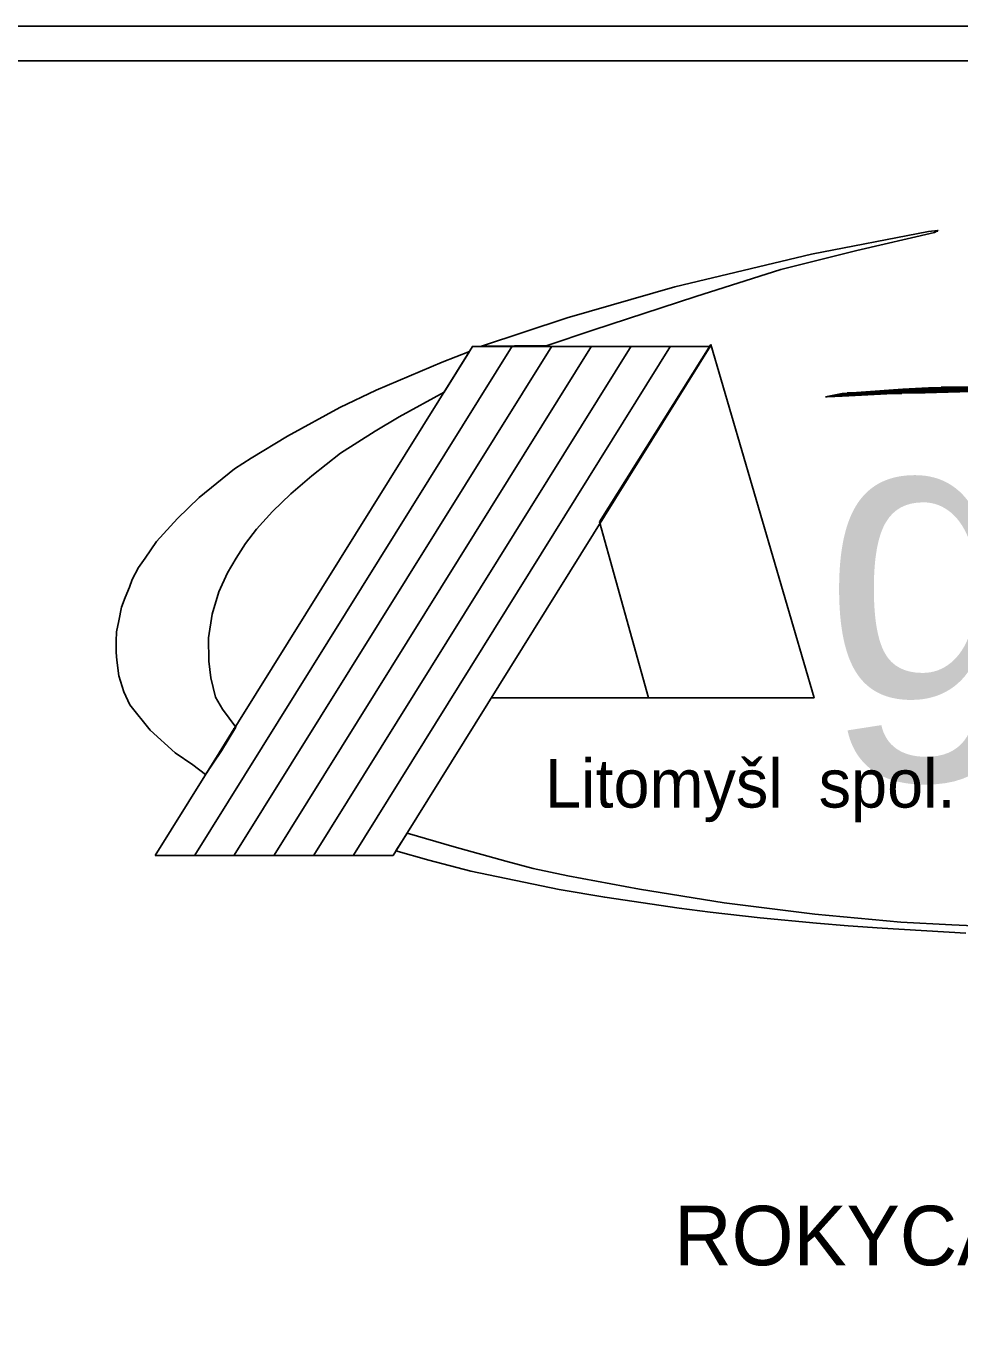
# Model space of a CAD drawing. Extents: x -5481 to -5365, y -3322 to -3178.
# Drawn here: x -5371.921 to -5369.567, y -3316.108 to -3312.83 of the extents above; entities that cross this region are included whole.
import ezdxf

# ---------------------------------------------------------------- set-up
doc = ezdxf.new("R2010")
doc.units = 0
doc.layers.add('Nová vrstva (0)', color=7, linetype='Continuous')

msp = doc.modelspace()

# ---------------------------------------------------------------- linework, layer by layer
at = {"layer": 'Nová vrstva (0)'}
for p, q in [((-5369.6242, -3313.347), (-5369.6232, -3313.347)), ((-5369.6198, -3313.346), (-5369.6195, -3313.346)), ((-5371.4954, -3314.9204), (-5370.696, -3313.6369)), ((-5371.3961, -3314.9204), (-5370.5962, -3313.6369)), ((-5371.2956, -3314.9204), (-5370.4962, -3313.6369)), ((-5371.1957, -3314.9204), (-5370.3963, -3313.6369)), ((-5371.1957, -3314.9204), (-5370.3963, -3313.6369)), ((-5371.0957, -3314.9204), (-5370.2964, -3313.6369)), ((-5369.9059, -3313.7651), (-5369.9018, -3313.7651)), ((-5369.9018, -3313.7639), (-5369.8828, -3313.7639)), ((-5369.8976, -3313.7629), (-5369.8639, -3313.7629)), ((-5369.8936, -3313.7625), (-5369.8471, -3313.7625)), ((-5369.8894, -3313.7614), (-5369.8312, -3313.7614)), ((-5369.8852, -3313.7607), (-5369.8154, -3313.7607)), ((-5369.8809, -3313.7598), (-5369.7998, -3313.7598)), ((-5369.8768, -3313.759), (-5369.7837, -3313.759)), ((-5369.8724, -3313.7583), (-5369.7678, -3313.7583)), ((-5369.8683, -3313.7575), (-5369.752, -3313.7575)), ((-5369.8639, -3313.7565), (-5369.7361, -3313.7565)), ((-5369.86, -3313.7561), (-5369.7136, -3313.7561)), ((-5369.8512, -3313.7551), (-5369.6845, -3313.7551)), ((-5369.8394, -3313.7546), (-5369.6552, -3313.7546)), ((-5369.8278, -3313.7537), (-5369.6261, -3313.7537)), ((-5369.8164, -3313.7529), (-5369.5968, -3313.7529)), ((-5369.8045, -3313.7522), (-5369.5676, -3313.7522)), ((-5369.793, -3313.7514), (-5369.5113, -3313.7514)), ((-5369.7811, -3313.7504), (-5369.4275, -3313.7504)), ((-5369.7695, -3313.7498), (-5368.621, -3313.7498)), ((-5369.758, -3313.7487), (-5368.6326, -3313.7487)), ((-5369.7463, -3313.7483), (-5368.6441, -3313.7483)), ((-5369.7346, -3313.7473), (-5368.6562, -3313.7473)), ((-5369.7228, -3313.7461), (-5368.668, -3313.7461)), ((-5369.7114, -3313.7456), (-5368.6794, -3313.7456)), ((-5369.6955, -3313.7448), (-5368.6955, -3313.7448)), ((-5369.6792, -3313.7442), (-5368.7116, -3313.7442)), ((-5369.6633, -3313.7431), (-5368.7278, -3313.7431)), ((-5369.647, -3313.7423), (-5368.7438, -3313.7423)), ((-5369.6148, -3313.7409), (-5368.7757, -3313.7409)), ((-5370.7492, -3314.5238), (-5370.3526, -3314.5238)), ((-5371.4657, -3314.713), (-5371.3961, -3314.6009))]:
    msp.add_line(p, q, dxfattribs=at)
for points in [[(-5383.7945, -3312.83), (-5366.2945, -3312.83), (-5366.2945, -3320.83), (-5383.7945, -3320.83)], [(-5383.6744, -3312.9179), (-5366.3744, -3312.9179), (-5366.3744, -3320.7179), (-5383.6744, -3320.7179)], [(-5370.7732, -3313.6369), (-5370.5573, -3313.5656), (-5370.2855, -3313.4876), (-5369.9413, -3313.4054), (-5369.6464, -3313.348), (-5369.623, -3313.3453), (-5369.6314, -3313.3509), (-5369.8269, -3313.3958), (-5370.0186, -3313.444), (-5370.2326, -3313.512), (-5370.4923, -3313.5966), (-5370.6075, -3313.6357)], [(-5370.1954, -3313.633), (-5369.9348, -3314.5235), (-5370.3526, -3314.5238), (-5370.476, -3314.0799)], [(-5371.4684, -3314.7169), (-5371.5008, -3314.693), (-5371.5447, -3314.6623), (-5371.6084, -3314.6054), (-5371.6595, -3314.5411), (-5371.6745, -3314.5086), (-5371.687, -3314.4681), (-5371.6925, -3314.4292), (-5371.694, -3314.4099), (-5371.694, -3314.3806), (-5371.6932, -3314.3577), (-5371.687, -3314.3299), (-5371.6807, -3314.2952), (-5371.6712, -3314.2709), (-5371.6602, -3314.2448), (-5371.6532, -3314.2258), (-5371.6374, -3314.195), (-5371.6209, -3314.172), (-5371.5919, -3314.1298), (-5371.5393, -3314.0719), (-5371.4843, -3314.0189), (-5371.4402, -3313.9825), (-5371.3955, -3313.9465), (-5371.3538, -3313.9199), (-5371.262, -3313.8643), (-5371.13, -3313.7917), (-5371.0388, -3313.7481), (-5370.8724, -3313.6771), (-5370.8032, -3313.6504), (-5370.8668, -3313.7531), (-5370.9808, -3313.8157), (-5371.0411, -3313.8513), (-5371.1284, -3313.9073), (-5371.2007, -3313.9639), (-5371.2534, -3314.0092), (-5371.2998, -3314.0544), (-5371.3398, -3314.0988), (-5371.368, -3314.1351), (-5371.3917, -3314.1715), (-5371.4129, -3314.2089), (-5371.4348, -3314.2567), (-5371.4521, -3314.313), (-5371.4614, -3314.3726), (-5371.46, -3314.4317), (-5371.4552, -3314.4731), (-5371.4434, -3314.5222), (-5371.4254, -3314.5524), (-5371.3924, -3314.598), (-5371.4286, -3314.6576)]]:
    msp.add_lwpolyline(points, close=True, dxfattribs=at)
for points in [[(-5371.5959, -3314.9214), (-5370.996, -3314.9214), (-5370.1965, -3313.6377), (-5370.7961, -3313.6377), (-5371.5959, -3314.9214)], [(-5371.3961, -3314.6009), (-5371.397, -3314.5996)], [(-5371.4668, -3314.712), (-5371.4657, -3314.713)], [(-5369.4225, -3315.104), (-5369.5875, -3315.0962), (-5369.7161, -3315.0893), (-5369.9327, -3315.069), (-5370.1619, -3315.0405), (-5370.3749, -3315.0061), (-5370.5558, -3314.9724), (-5370.6432, -3314.9541), (-5370.7115, -3314.9353), (-5370.8421, -3314.8992), (-5370.9606, -3314.8654), (-5370.9889, -3314.9098), (-5370.906, -3314.9331), (-5370.8001, -3314.9605), (-5370.577, -3315.0069), (-5370.4627, -3315.0266), (-5370.2752, -3315.0545), (-5370.1967, -3315.0645), (-5370.0712, -3315.0782), (-5369.9287, -3315.0916), (-5369.8489, -3315.099), (-5369.7634, -3315.1043), (-5369.5523, -3315.1173)]]:
    msp.add_lwpolyline(points, dxfattribs=at)

# ---------------------------------------------------------------- texts
for s, height, p in [('groprojekce', 0.721382, (-5369.9124, -3314.525)), ('Litomyšl  spol. s.r.o.', 0.122081, (-5370.6128, -3314.8005)), (' ROKYCANOVA 114/IV', 0.15, (-5370.3433, -3315.9545))]:
    msp.add_text(s, height=height, dxfattribs=at).set_placement(p)

doc.saveas('drawing.dxf')
